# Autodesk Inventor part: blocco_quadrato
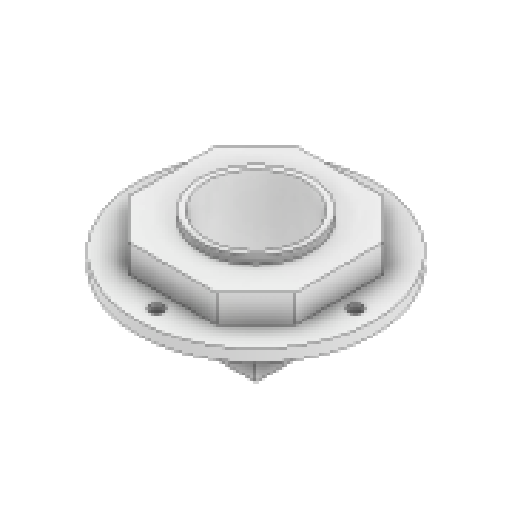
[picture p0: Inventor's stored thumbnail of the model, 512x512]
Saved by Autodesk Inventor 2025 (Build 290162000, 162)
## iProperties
Created: 2025-05
Part Number: blocco_quadrato
Material: Plastica ABS
Document SubType Name: Modeling
Designer: R5800u
Density: 1.06 g/cm^3
Appearance: Liscia - Bianco
Author: R5800u
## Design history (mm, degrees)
sketch "Schizzo1"
  geometry: L1 (17.5, 17.5)-(-17.5, 17.5); L2 (-17.5, 17.5)-(-17.5, -17.5); L3 (-17.5, -17.5)-(17.5, -17.5); L4 (17.5, -17.5)-(17.5, 17.5); L5 (17.5, 17.5)-(-17.5, -17.5); L6 (-17.5, 17.5)-(17.5, -17.5); 1 further point
  constraints: 12 end point, 2 midpoint, 2 parallel, 1 horizontal, 1 perpendicular
  dimensions: "d0" = 35 distance of L3.end L2.end; "d1" = 35 distance of L2.end L1.end
extrude "Estrusione1" new body sketch "Schizzo1" distance "d2" = 8; taper "d3" = 0 deg
sketch "Schizzo2"
  geometry: C1 r 12.5 at (0, 0); 1 further point
  constraints: 1 centre point, 1 coincident
  dimensions: "d4" = 25 diameter of C1
extrude "Estrusione2" cut sketch "Schizzo2" extent not by distance; stored distance "d5" = 0; taper "d6" = 0 deg
sketch "Schizzo6"
  geometry: L1 (-17.5, -17.5)-(17.5, -17.5) reference; L2 (17.5, -17.5)-(17.5, 17.5) reference; L3 (17.5, 17.5)-(-17.5, 17.5) reference; L4 (-17.5, 17.5)-(-17.5, -17.5) reference; L5 (-17.5, -17.5)-(17.5, -17.5) reference; L6 (-21, -21)-(21, -21); L7 (21, -21)-(21, 21); L8 (21, 21)-(-21, 21); L9 (-21, 21)-(-21, -21); L10 (-21, -21)-(21, 21); L11 (21, -21)-(-21, 21); C1 r 12.5 at (0, 0) reference; C2 r 30 at (0, 0); C3 r 12.5 at (0, 0) reference; A1 r 24.749 centre (0, 0) between (17.5, -17.5) and (-17.5, -17.5); 5 further points
  constraints: 12 end point, 2 centre point, 2 coincident, 2 midpoint, 2 parallel, 1 horizontal, 1 perpendicular, 1 point on circle, 1 vertical alignment
  dimensions: "d18" = 60 diameter of C2; "d54" = 42 distance of L8.end L7.end; "d55" = 42 distance of L6.end L7.end
extrude "Estrusione5" join sketch "Schizzo6" distance "d13" = 3; taper "d14" = 0 deg
sketch "Schizzo7"
  geometry: 2 further points
  dimensions: "d20" = 25 distance of point (0, 0) point (25, 0)
hole "Foro1" sketch "Schizzo7" at (25, 0) diameter "d21" = 3.4; stored, may be unused: countersink angle "d25" = 90 deg, drill point angle "d27" = 118 deg; dims "d22" = 10, "d23" = 6.3, "d24" = 2, "d26" = 8
pattern_circular "Serie circolare1" dims angle "d29" = 360 deg
sketch "Schizzo8"
  geometry: L1 (17.5, -17.5)-(17.5, 17.5) reference; L2 (17.5, 17.5)-(-17.5, 17.5) reference; L3 (-17.5, 17.5)-(-17.5, -17.5) reference; L4 (-17.5, -17.5)-(17.5, -17.5) reference; L5 (-21, -21)-(21, -21); L6 (21, -21)-(21, 21); L7 (21, 21)-(-21, 21); L8 (-21, 21)-(-21, -21); L9 (-21, -21)-(21, 21); L10 (21, -21)-(-21, 21); C1 r 12.5 at (0, 0) reference; 1 further point
  constraints: 12 end point, 2 midpoint, 2 parallel, 1 horizontal, 1 perpendicular
  dimensions: "d56" = 42 distance of L7.end L6.end; "d57" = 42 distance of L6.end L5.end
extrude "Estrusione6" join sketch "Schizzo8" distance "d34" = 10; taper "d35" = 0 deg
chamfer "Smusso3" distance "d36" = 10; stored, may be unused: second distance "d37" = 2, angle "d38" = 45 deg
sketch "Schizzo9"
  geometry: L1 (2.8, -17.2)-(-2.8, -17.2); L2 (-2.8, -17.2)-(-2.8, -14.8); L3 (-2.8, -14.8)-(2.8, -14.8); L4 (2.8, -14.8)-(2.8, -17.2); L5 (2.8, -17.2)-(-2.8, -14.8); L6 (-2.8, -17.2)-(2.8, -14.8); L7 (14.142, -10.182)-(10.182, -14.142); L8 (10.182, -14.142)-(8.485, -12.445); L9 (8.485, -12.445)-(12.445, -8.485); L10 (12.445, -8.485)-(14.142, -10.182); L11 (14.142, -10.182)-(8.485, -12.445); L12 (10.182, -14.142)-(12.445, -8.485); L13 (17.2, 2.8)-(17.2, -2.8); L14 (17.2, -2.8)-(14.8, -2.8); L15 (14.8, -2.8)-(14.8, 2.8); L16 (14.8, 2.8)-(17.2, 2.8); L17 (17.2, 2.8)-(14.8, -2.8); L18 (17.2, -2.8)-(14.8, 2.8); L19 (10.182, 14.142)-(14.142, 10.182); L20 (14.142, 10.182)-(12.445, 8.485); L21 (12.445, 8.485)-(8.485, 12.445); L22 (8.485, 12.445)-(10.182, 14.142); L23 (10.182, 14.142)-(12.445, 8.485); L24 (14.142, 10.182)-(8.485, 12.445); L25 (-2.8, 17.2)-(2.8, 17.2); L26 (2.8, 17.2)-(2.8, 14.8); L27 (2.8, 14.8)-(-2.8, 14.8); L28 (-2.8, 14.8)-(-2.8, 17.2); L29 (-2.8, 17.2)-(2.8, 14.8); L30 (2.8, 17.2)-(-2.8, 14.8); L31 (-14.142, 10.182)-(-10.182, 14.142); L32 (-10.182, 14.142)-(-8.485, 12.445); L33 (-8.485, 12.445)-(-12.445, 8.485); L34 (-12.445, 8.485)-(-14.142, 10.182); L35 (-14.142, 10.182)-(-8.485, 12.445); L36 (-10.182, 14.142)-(-12.445, 8.485); L37 (-17.2, -2.8)-(-17.2, 2.8); L38 (-17.2, 2.8)-(-14.8, 2.8); L39 (-14.8, 2.8)-(-14.8, -2.8); L40 (-14.8, -2.8)-(-17.2, -2.8); L41 (-17.2, -2.8)-(-14.8, 2.8); L42 (-17.2, 2.8)-(-14.8, -2.8); L43 (-10.182, -14.142)-(-14.142, -10.182); L44 (-14.142, -10.182)-(-12.445, -8.485); L45 (-12.445, -8.485)-(-8.485, -12.445); L46 (-8.485, -12.445)-(-10.182, -14.142); L47 (-10.182, -14.142)-(-12.445, -8.485); L48 (-14.142, -10.182)-(-8.485, -12.445); C1 r 12.5 at (0, 0) reference; 9 further points
  constraints: 96 end point, 2 midpoint, 2 parallel, 1 horizontal, 1 perpendicular, 89 other
  dimensions: "d39" = 5.6 distance of L2.end L3.end; "d40" = 2.4 distance of L1.end L2.end; "d41" = 16 distance of C1.centre point (0, -16); "d60" = 360 deg dimension on point (0, 0) L1.start (derived)
extrude "Estrusione7" cut sketch "Schizzo9" distance "d42" = 7; taper "d43" = 0 deg
sketch "Schizzo13"
  geometry: L1 (14.142, 7)-(0, 7) reference; L2 (0, 7)-(0, 0) reference; L3 (0, 0)-(14.142, 0) reference; L4 (14.142, 0)-(14.142, 7) reference; L5 (0, 0)-(-15.556, 0) reference; L6 (14.142, 7)-(0, 0); L7 (0, 0)-(0, 7); L8 (0, 0)-(14.142, 0) reference; L9 (0, 7)-(14.142, 0); 2 further points
  constraints: 6 end point, 1 collinear, 1 midpoint
hole "Foro4" sketch "Schizzo13" at (7.071, 3.5) diameter "d69" = 3.4; stored, may be unused: countersink angle "d73" = 90 deg, drill point angle "d75" = 0 deg; dims "d70" = 6, "d71" = 5.5, "d72" = 3, "d74" = 8
sketch "Schizzo14"
  geometry: C1 r 14 at (0, 0); C2 r 12.5 at (0, 0) reference; 1 further point
  constraints: 1 centre point, 1 coincident
  dimensions: "d76" = 28 diameter of C1
extrude "Estrusione9" join sketch "Schizzo14" distance "d77" = 2; taper "d78" = 0 deg
sketch "Schizzo15"
  geometry: 1 further point
sketch "Schizzo16"
  geometry: 1 further point
sketch "Schizzo17"
  geometry: L1 (10.304, 3.5)-(8.688, 0.7); L2 (8.688, 0.7)-(5.454, 0.7); L3 (5.454, 0.7)-(3.838, 3.5); L4 (3.838, 3.5)-(5.454, 6.3); L5 (5.454, 6.3)-(8.688, 6.3); L6 (8.688, 6.3)-(10.304, 3.5); C1 r 1.7 at (7.071, 3.5) reference; 2 further points
  constraints: 12 end point, 1 coincident, 13 other
  dimensions: "d79" = 5.6 distance between parallel lines of L5 L2
extrude "Estrusione10" cut sketch "Schizzo17" distance "d80" = 3; taper "d81" = 0 deg
node "Solido1"
node "Linea chiusa proiettata2"
node "Linea chiusa proiettata3"
node "Schizzo - Serie circolare1" dims "d60" = 360 deg (derived)
node "Linea chiusa proiettata5"
